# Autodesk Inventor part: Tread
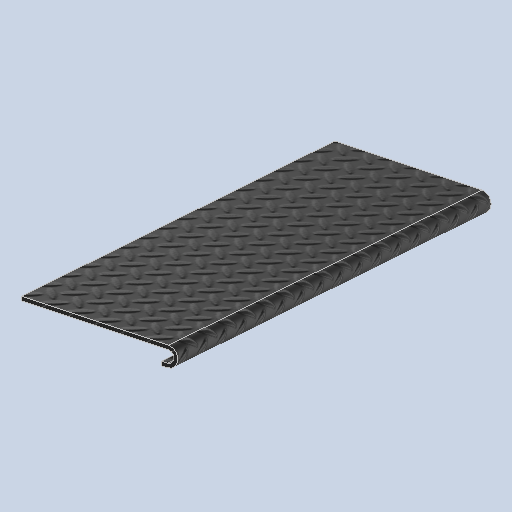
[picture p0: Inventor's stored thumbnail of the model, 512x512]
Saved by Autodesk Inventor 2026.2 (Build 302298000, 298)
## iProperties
RuleStatus: InUse
Created: 2022-06
Part Number: Tread
Material: Steel, Wrought
Document SubType Name: Modeling
Designer: reaumed
Density: 7.85 g/cm^3
Appearance: Diamond plate 2 - Dark Gray
Mass: 13075.7 g
Surface Area: 5392.46 cm^2
Volume: 1665.69 cm^3
AfterMaterialChange0: Appearance Override
Author: reaumed
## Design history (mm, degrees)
workplane "Work Plane (Rise)"
sketch "Tread Profile Sketch"
  geometry: L1 (0, 342.9)-(254, 342.9); L2 (254, 342.9)-(254, -342.9); L3 (254, -342.9)-(0, -342.9); L4 (0, -342.9)-(0, 342.9); 2 further points
  constraints: 8 end point, 2 parallel, 1 coincident, 1 horizontal, 1 midpoint, 1 perpendicular
  dimensions: "d4" = 685.8 distance of L1.end L2.end (derived); "d5" = 254 distance of L1.start L1.end (derived)
extrude "Tread Extrusion" new body sketch "Tread Profile Sketch" distance "d6" = 31.75 (derived); taper "d7" = 0 deg
fillet "Fillet1" dims "d9" = 15.875 (derived)
shell "Shell1" dims "d10" = 6.35
thicken "Thicken1" dims "d11" = 9.525 (= NosingGap), "d12" = 9.525 (= NosingGap)
body "Solid2"
other parameters: "d8" = -190.5 (derived), "StringerThickness" = 38.1 [user parameter; used in 1 equation term], "NosingGap" = 9.525 [user parameter; used in 2 equation terms]
